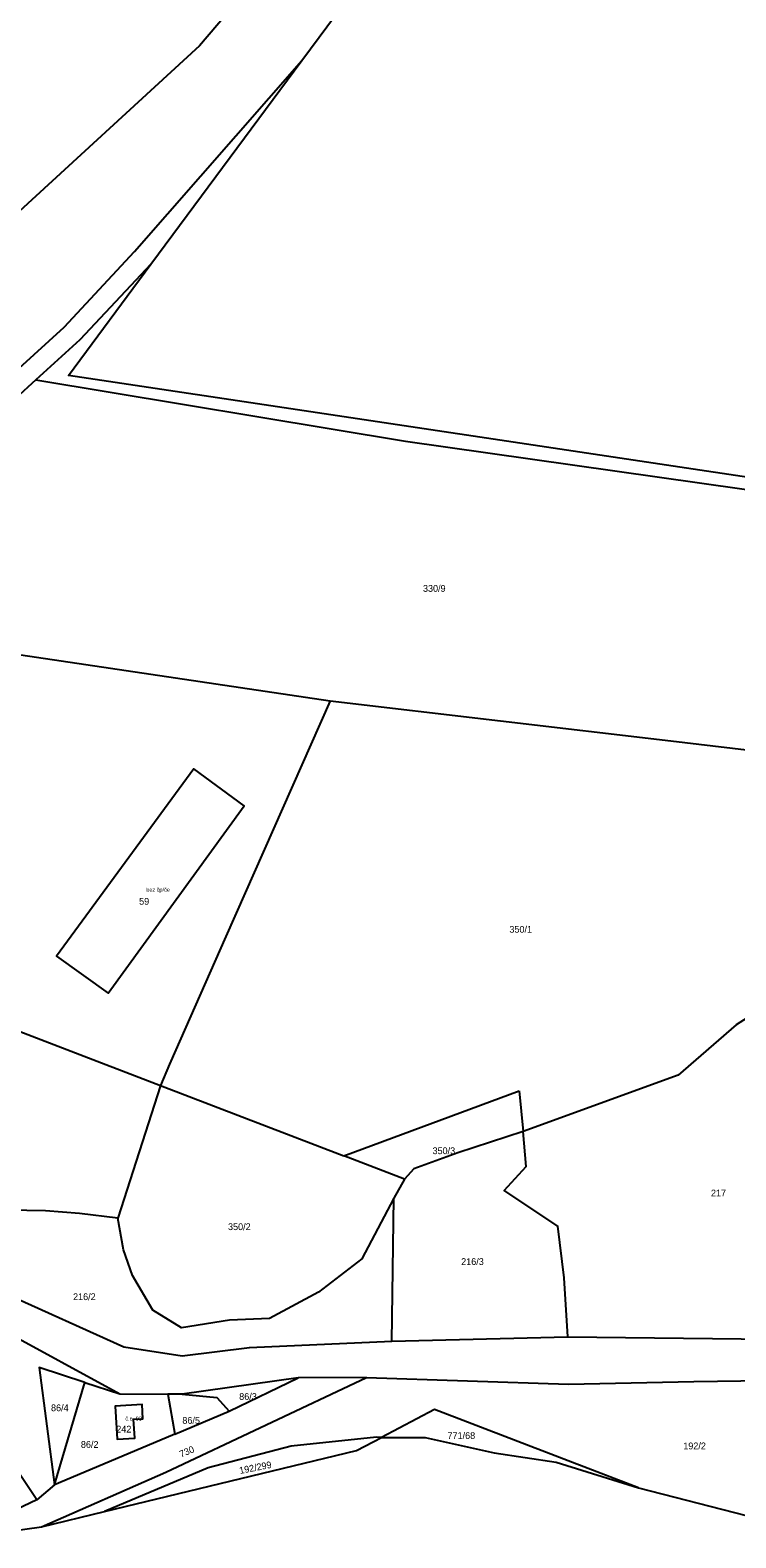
# Model space of a CAD drawing. Extents: x -887272 to -880188, y -1026687 to -1021896.
# Drawn here: x -882815.9 to -882638.7, y -1024095.3 to -1023716.8 of the extents above; entities that cross this region are included whole.
import ezdxf

# ---------------------------------------------------------------- set-up
doc = ezdxf.new("R2010")
doc.units = 0
for name, color, linetype in [('Definiční body', 7, 'Continuous'), ('Hranice parcel', 7, 'Continuous'), ('Parcelní čísla', 7, 'Continuous'), ('Polygon budovy', 7, 'Continuous')]:
    doc.layers.add(name, color=color, linetype=linetype)

msp = doc.modelspace()

# ---------------------------------------------------------------- linework, layer by layer
at = {"layer": 'Hranice parcel'}
for p, q in [((-882785.58, -1023775.53), (-882747.67, -1023724.4)), ((-882818.72, -1023801.69), (-882807.36, -1023791.35)), ((-882889.66, -1023862.97), (-882740.58, -1023885.14)), ((-882783.22, -1023981.7), (-882793.94, -1024015.04)), ((-882783.22, -1023981.7), (-882737.14, -1023999.37)), ((-882737.14, -1023999.37), (-882693.13, -1023983.08)), ((-882693.13, -1023983.08), (-882692.14, -1023993.26)), ((-882721.92, -1024005.21), (-882737.14, -1023999.37)), ((-882721.92, -1024005.21), (-882724.61, -1024010)), ((-882725.1, -1024045.88), (-882724.61, -1024010)), ((-882823.53, -1024042.74), (-882793.44, -1024059.16)), ((-882725.1, -1024045.88), (-882680.86, -1024044.8)), ((-882680.86, -1024044.8), (-882603.02, -1024045.76)), ((-882809.82, -1024082), (-882802.19, -1024056.31)), ((-882802.19, -1024056.31), (-882793.44, -1024059.16)), ((-882748.62, -1024055.1), (-882777.74, -1024059.24)), ((-882765.98, -1024063.52), (-882748.62, -1024055.1)), ((-882731.42, -1024055.06), (-882748.62, -1024055.1)), ((-882793.44, -1024059.16), (-882781.34, -1024059.22)), ((-882777.74, -1024059.24), (-882781.34, -1024059.22)), ((-882781.34, -1024059.22), (-882779.62, -1024069.26)), ((-882779.62, -1024069.26), (-882765.98, -1024063.52)), ((-882771.25, -1024077.69), (-882797.22, -1024088.67)), ((-882683.78, -1024076.31), (-882663.14, -1024082.74)), ((-882809.82, -1024082), (-882814.22, -1024085.76)), ((-882663.14, -1024082.74), (-882636.1, -1024089.7)), ((-882814.22, -1024085.76), (-882828.88, -1024092.62)), ((-882813.04, -1024092.5), (-882797.22, -1024088.67)), ((-882832.64, -1024095.28), (-882813.04, -1024092.5))]:
    msp.add_line(p, q, dxfattribs=at)
for points in [[(-882747.67, -1023724.4), (-882728.63, -1023698.68), (-882663.18, -1023610.28), (-882597.73, -1023521.88), (-882532.27, -1023433.49), (-882456.11, -1023330.63)], [(-882058.02, -1023479.44), (-882103.84, -1023528.65), (-882178.79, -1023609.12), (-882251.38, -1023686.73), (-882326.67, -1023766.9), (-882416, -1023862), (-882806.28, -1023803.54), (-882785.58, -1023775.53)], [(-882726.3, -1023648.88), (-882721.13, -1023653.25), (-882736.57, -1023677.46), (-882773.39, -1023720.75), (-882821.66, -1023765.08), (-882853.85, -1023796.42)], [(-882807.36, -1023791.35), (-882789.69, -1023772.36), (-882747.67, -1023724.4)], [(-882785.58, -1023775.53), (-882803.48, -1023794.55), (-882814.51, -1023804.61)], [(-882814.51, -1023804.61), (-882840.14, -1023827.98), (-882853.74, -1023840.13), (-882872.92, -1023853.76), (-882889.66, -1023862.97)], [(-882814.51, -1023804.61), (-882721.64, -1023820.02), (-882498.98, -1023851.5), (-882542.88, -1023902.92), (-882550.84, -1023907.6)], [(-882740.58, -1023885.14), (-882766.74, -1023944.3), (-882780.94, -1023976.36), (-882783.22, -1023981.7)], [(-882740.58, -1023885.14), (-882655.04, -1023895.24), (-882550.84, -1023907.6)], [(-882762.16, -1023911.56), (-882774.78, -1023902.26), (-882809.32, -1023949.3), (-882796.36, -1023958.56), (-882762.16, -1023911.56)], [(-882600.7, -1023942.36), (-882638.58, -1023966.48), (-882653.18, -1023979.16), (-882692.14, -1023993.26)], [(-882898.5, -1023986.86), (-882880.66, -1023944.34), (-882783.22, -1023981.7)], [(-882793.94, -1024015.04), (-882803.56, -1024013.88), (-882812.08, -1024013.2), (-882826.3, -1024012.98), (-882839.2, -1024006.98), (-882862.38, -1023994.9), (-882881, -1023994.54)], [(-882881, -1023994.54), (-882856.7, -1024014.52), (-882822.42, -1024033.78), (-882792.42, -1024047.32), (-882777.72, -1024049.62), (-882760.86, -1024047.48), (-882725.1, -1024045.88)], [(-882692.14, -1023993.26), (-882708.54, -1023998.62), (-882719.6, -1024002.66), (-882721.92, -1024005.21)], [(-882680.86, -1024044.8), (-882681.84, -1024029.98), (-882683.36, -1024017.06), (-882696.86, -1024008.06), (-882691.34, -1024002.08), (-882692.14, -1023993.26)], [(-882724.61, -1024010), (-882732.62, -1024025.22), (-882743.54, -1024033.58), (-882755.84, -1024040.2), (-882765.86, -1024040.64), (-882777.88, -1024042.58), (-882785.12, -1024038.16), (-882790.2, -1024029.44), (-882792.5, -1024022.96), (-882793.94, -1024015.04)], [(-882802.19, -1024056.31), (-882813.68, -1024052.56), (-882809.82, -1024082)], [(-882813.04, -1024092.5), (-882781.82, -1024078.82), (-882731.42, -1024055.06)], [(-882731.42, -1024055.06), (-882680.72, -1024056.68), (-882649.26, -1024056.02), (-882607.88, -1024055.44), (-882600.66, -1024055.78), (-882545.75, -1024055.18)], [(-882777.74, -1024059.24), (-882769, -1024060.06), (-882765.98, -1024063.52)], [(-882789.63, -1024070.25), (-882789.93, -1024065.53), (-882787.6, -1024065.38), (-882787.83, -1024061.82), (-882794.61, -1024062.25), (-882794.09, -1024070.53), (-882789.63, -1024070.25)], [(-882663.14, -1024082.74), (-882714.34, -1024063.04), (-882727.69, -1024070.05)], [(-882779.62, -1024069.26), (-882805.64, -1024080.22), (-882809.82, -1024082)], [(-882797.22, -1024088.67), (-882734, -1024073.36), (-882727.69, -1024070.05)], [(-882727.69, -1024070.05), (-882728.92, -1024070.04), (-882750.38, -1024072.23), (-882771.25, -1024077.69)], [(-882727.69, -1024070.05), (-882716.71, -1024070.12), (-882699.4, -1024073.96), (-882683.78, -1024076.31)], [(-882814.22, -1024085.76), (-882821.92, -1024074.22), (-882827.7, -1024079.54), (-882832.06, -1024086.88), (-882828.88, -1024092.62)]]:
    msp.add_lwpolyline(points, dxfattribs=at)
at = {"layer": 'Polygon budovy'}
for points in [[(-882774.78, -1023902.26), (-882809.32, -1023949.3), (-882796.36, -1023958.56), (-882762.16, -1023911.56)], [(-882794.09, -1024070.53), (-882789.63, -1024070.25), (-882789.93, -1024065.53), (-882787.6, -1024065.38), (-882787.83, -1024061.82), (-882794.61, -1024062.25)]]:
    msp.add_lwpolyline(points, close=True, dxfattribs=at)

# ---------------------------------------------------------------- texts
at = {"layer": 'Definiční body'}
for s, p in [('bez čp/če', (-882786.75, -1023933.08)), ('č.e. 93', (-882792.01, -1024065.83))]:
    msp.add_text(s, height=1, dxfattribs=at).set_placement(p)
at = {"layer": 'Parcelní čísla'}
for s, p in [('330/9', (-882717.27, -1023857.8)), ('59', (-882788.56, -1023936.35)), ('350/1', (-882695.57, -1023943.38)), ('350/3', (-882714.87, -1023998.96)), ('217', (-882644.95, -1024009.57)), ('350/2', (-882766.23, -1024018.03)), ('216/3', (-882707.68, -1024026.79)), ('216/2', (-882805.15, -1024035.6)), ('86/3', (-882763.42, -1024060.65)), ('86/4', (-882810.68, -1024063.49)), ('242', (-882794.3, -1024068.84)), ('86/5', (-882777.7, -1024066.65)), ('86/2', (-882803.18, -1024072.69)), ('771/68', (-882711.11, -1024070.46)), ('192/2', (-882651.9, -1024073.05))]:
    msp.add_text(s, height=1.7, dxfattribs=at).set_placement(p)
for s, rotation, p in [('730', 23, (-882778.01, -1024075.15)), ('192/299', 11, (-882763.23, -1024079.25))]:
    msp.add_text(s, height=1.7, rotation=rotation, dxfattribs=at).set_placement(p)

doc.saveas('drawing.dxf')
